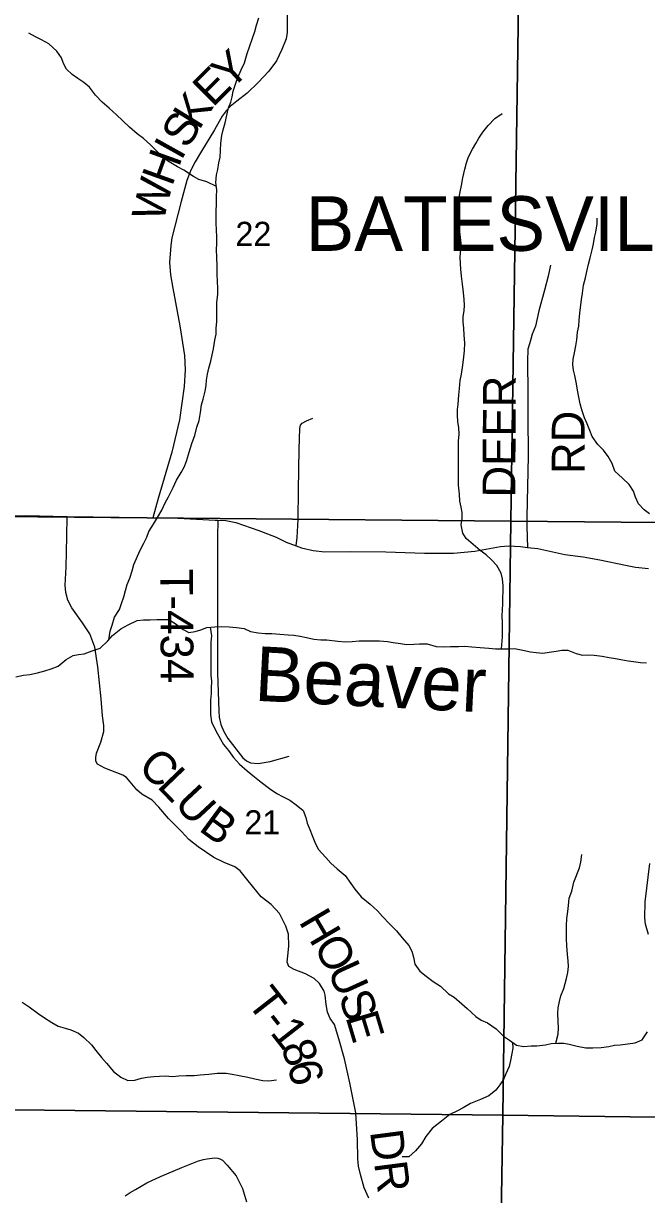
# Model space of a CAD drawing. Extents: x 2043100 to 2470832, y 443715 to 810583.
# Drawn here: x 2302542 to 2308244, y 693056 to 703774 of the extents above; entities that cross this region are included whole.
import ezdxf

# ---------------------------------------------------------------- set-up
doc = ezdxf.new("R2010")
doc.units = 0
for name, color, linetype in [('GM_X_Corporation_Text', 7, 'Continuous'), ('GM_X_County_Road', 7, 'Continuous'), ('GM_X_County_Road_Text', 7, 'Continuous'), ('GM_X_Minor_River', 7, 'Continuous'), ('GM_X_Minor_River_Text', 7, 'Continuous'), ('GM_X_Section', 7, 'Continuous'), ('GM_X_Section_Text', 7, 'Continuous'), ('GM_X_State_Route', 7, 'Continuous'), ('GM_X_Township_Road', 7, 'Continuous'), ('GM_X_Township_Road_Text', 7, 'Continuous')]:
    doc.layers.add(name, color=color, linetype=linetype)

msp = doc.modelspace()

# ---------------------------------------------------------------- linework, layer by layer
at = {"layer": 'GM_X_County_Road'}
msp.add_lwpolyline([(2304954, 703932), (2304956, 703759), (2304954, 703691), (2304945, 703633), (2304908, 703535), (2304857, 703431), (2304788, 703338), (2304691, 703234), (2304590, 703137), (2304495, 703062), (2304433, 703014), (2304396, 702974), (2304362, 702925), (2304291, 702799), (2304171, 702606), (2304114, 702508), (2304073, 702430), (2304038, 702338), (2303986, 702144), (2303899, 701812), (2303892, 701742), (2303879, 701586), (2303888, 701473), (2303909, 701351), (2303973, 701007), (2304017, 700734), (2304022, 700604), (2304014, 700452), (2303969, 700145), (2303900, 699851), (2303774, 699427), (2303726, 699250)], dxfattribs=at)
at = {"layer": 'GM_X_Minor_River'}
for points in [[(2303324, 698134), (2303336, 698211), (2303354, 698266), (2303376, 698340), (2303420, 698410), (2303439, 698464), (2303461, 698527), (2303477, 698583), (2303491, 698639), (2303515, 698697), (2303537, 698763), (2303553, 698822), (2303577, 698876), (2303607, 698948), (2303645, 699018), (2303671, 699073), (2303690, 699123), (2303732, 699193), (2303768, 699251), (2303808, 699320), (2303838, 699386), (2303870, 699442), (2303912, 699526), (2303942, 699593), (2303986, 699663), (2304012, 699713), (2304034, 699767), (2304053, 699828), (2304069, 699880), (2304087, 699938), (2304111, 700002), (2304129, 700080), (2304149, 700141), (2304161, 700213), (2304171, 700283), (2304187, 700335), (2304204, 700409), (2304214, 700460), (2304218, 700510), (2304226, 700564), (2304238, 700618), (2304256, 700682), (2304270, 700742), (2304282, 700797), (2304295, 700875), (2304305, 700931), (2304307, 700983), (2304311, 701047), (2304311, 701102), (2304313, 701162), (2304311, 701224), (2304321, 701292), (2304320, 701348), (2304318, 701416), (2304316, 701476), (2304316, 701555), (2304312, 701633), (2304310, 701705), (2304311, 701757), (2304311, 701819), (2304309, 701885), (2304307, 701946), (2304307, 702056), (2304309, 702120), (2304310, 702190), (2304312, 702252), (2304304, 702319), (2304310, 702389), (2304320, 702439), (2304330, 702499), (2304342, 702549), (2304345, 702611), (2304349, 702678), (2304359, 702750), (2304369, 702800), (2304389, 702866), (2304403, 702934), (2304419, 703001), (2304439, 703053), (2304452, 703103), (2304462, 703153), (2304486, 703229), (2304504, 703280), (2304536, 703350), (2304564, 703414), (2304590, 703499), (2304610, 703559), (2304639, 703639), (2304659, 703701), (2304675, 703757), (2304695, 703826)], [(2304309, 702283), (2304220, 702324), (2304148, 702346), (2304098, 702374), (2304011, 702432), (2303953, 702462), (2303861, 702516), (2303782, 702587), (2303706, 702663), (2303640, 702721), (2303582, 702763), (2303513, 702825), (2303451, 702883), (2303393, 702939), (2303327, 702999), (2303264, 703055), (2303202, 703117), (2303146, 703191), (2303094, 703233), (2303040, 703271), (2302989, 703307), (2302937, 703355), (2302909, 703409), (2302891, 703459), (2302847, 703521), (2302776, 703587), (2302706, 703623), (2302654, 703653), (2302592, 703686)], [(2306916, 698049), (2306926, 698161), (2306926, 698287), (2306924, 698352), (2306926, 698408), (2306930, 698462), (2306930, 698520), (2306932, 698576), (2306931, 698628), (2306925, 698692), (2306915, 698742), (2306873, 698812), (2306825, 698866), (2306775, 698912), (2306722, 698952), (2306594, 699060), (2306564, 699110), (2306549, 699186), (2306557, 699244), (2306557, 699297), (2306549, 699347), (2306535, 699401), (2306531, 699465), (2306523, 699549), (2306522, 699693), (2306524, 699761), (2306522, 699832), (2306522, 699892), (2306524, 699950), (2306528, 700014), (2306527, 700074), (2306517, 700132), (2306513, 700188), (2306515, 700241), (2306519, 700291), (2306525, 700371), (2306533, 700433), (2306540, 700505), (2306550, 700563), (2306564, 700646), (2306572, 700722), (2306578, 700778), (2306582, 700850), (2306575, 700922), (2306571, 700985), (2306565, 701041), (2306565, 701091), (2306575, 701145), (2306579, 701195), (2306575, 701247), (2306569, 701311), (2306560, 701389), (2306552, 701460), (2306546, 701526), (2306542, 701578), (2306538, 701636), (2306544, 701704), (2306547, 701760), (2306543, 701816), (2306537, 701867), (2306531, 701931), (2306523, 701999), (2306517, 702057), (2306519, 702113), (2306526, 702167), (2306540, 702232), (2306550, 702290), (2306564, 702360), (2306580, 702442), (2306596, 702500), (2306614, 702553), (2306652, 702623), (2306682, 702675), (2306709, 702725), (2306745, 702780), (2306795, 702840), (2306855, 702904), (2306923, 702951)], [(2308272, 699286), (2308222, 699322), (2308170, 699378), (2308142, 699438), (2308124, 699494), (2308085, 699556), (2308025, 699612), (2307955, 699676), (2307929, 699748), (2307894, 699810), (2307850, 699870), (2307798, 699920), (2307746, 699994), (2307724, 700050), (2307701, 700110), (2307677, 700164), (2307651, 700238), (2307637, 700294), (2307623, 700354), (2307613, 700418), (2307602, 700477), (2307588, 700551), (2307576, 700601), (2307570, 700653), (2307572, 700703), (2307584, 700759), (2307598, 700825), (2307605, 700880), (2307613, 700948), (2307623, 701004), (2307627, 701058), (2307635, 701122), (2307649, 701249), (2307657, 701307), (2307668, 701379), (2307684, 701445), (2307698, 701503), (2307714, 701570), (2307728, 701628), (2307746, 701702), (2307758, 701758), (2307768, 701814), (2307781, 701865), (2307791, 701941), (2307793, 701991)], [(2302473, 697794), (2302543, 697808), (2302601, 697816), (2302670, 697830), (2302738, 697849), (2302796, 697867), (2302860, 697891), (2302934, 697952), (2302996, 697990), (2303046, 698000), (2303098, 698006), (2303170, 698031), (2303244, 698057), (2303314, 698123), (2303358, 698173), (2303432, 698234), (2303502, 698270), (2303584, 698311), (2303642, 698317), (2303702, 698317), (2303764, 698319), (2303816, 698319), (2303873, 698318), (2303941, 698276), (2304003, 698226), (2304057, 698200), (2304115, 698208), (2304165, 698224), (2304221, 698247), (2304294, 698253), (2304354, 698255), (2304424, 698251), (2304492, 698247), (2304562, 698236), (2304620, 698210), (2304690, 698196), (2304754, 698190), (2304815, 698190), (2304889, 698185), (2304965, 698179), (2305015, 698175), (2305075, 698167), (2305131, 698155)], [(2304251, 698249), (2304262, 698168), (2304258, 698112), (2304256, 698052), (2304258, 698000), (2304256, 697930), (2304256, 697880), (2304258, 697810), (2304263, 697754), (2304261, 697691), (2304259, 697641), (2304255, 697581), (2304255, 697451), (2304263, 697383), (2304304, 697299), (2304344, 697225), (2304374, 697175), (2304418, 697119), (2304465, 697057), (2304519, 696995), (2304589, 696935), (2304657, 696879), (2304717, 696829), (2304794, 696773), (2304860, 696727), (2304920, 696697), (2304980, 696666), (2305039, 696624), (2305103, 696572), (2305125, 696506), (2305139, 696454), (2305163, 696396), (2305183, 696343), (2305210, 696281), (2305240, 696217), (2305310, 696141), (2305354, 696089), (2305413, 696036), (2305485, 695976), (2305539, 695904), (2305575, 695850), (2305633, 695782), (2305714, 695714), (2305782, 695654), (2305828, 695602), (2305893, 695534), (2305955, 695470), (2306007, 695404), (2306069, 695334), (2306097, 695282), (2306112, 695228), (2306124, 695166), (2306170, 695100), (2306226, 695056), (2306292, 695006), (2306359, 694964), (2306433, 694894), (2306485, 694861), (2306553, 694801), (2306604, 694759), (2306682, 694685), (2306732, 694653), (2306790, 694629), (2306868, 694573), (2306935, 694507), (2306989, 694469), (2307053, 694423), (2307117, 694410), (2307189, 694418), (2307239, 694418), (2307320, 694426), (2307370, 694438), (2307432, 694441), (2307486, 694441), (2307536, 694433), (2307610, 694413), (2307690, 694399), (2307754, 694398), (2307830, 694402), (2307899, 694410), (2307951, 694422), (2308003, 694427), (2308073, 694435), (2308141, 694445), (2308205, 694473), (2308253, 694544)], [(2305131, 698155), (2305199, 698139), (2305264, 698134), (2305318, 698132), (2305418, 698120), (2305488, 698116), (2305550, 698117), (2305614, 698123), (2305680, 698125), (2305799, 698125), (2305875, 698118), (2305927, 698110), (2305993, 698098), (2306049, 698090), (2306115, 698092), (2306167, 698097), (2306237, 698095), (2306320, 698071), (2306396, 698069), (2306450, 698071), (2306524, 698072), (2306582, 698074), (2306646, 698070), (2306722, 698064), (2306802, 698056), (2306861, 698051), (2306911, 698049), (2306981, 698051), (2307037, 698053), (2307113, 698039), (2307181, 698024), (2307233, 698016), (2307295, 698012), (2307354, 698020), (2307418, 698030), (2307468, 698037), (2307524, 698037), (2307600, 698009), (2307658, 697993), (2307714, 697997), (2307766, 697993), (2307837, 697984), (2307903, 697972), (2307959, 697962), (2308009, 697954), (2308075, 697942), (2308125, 697934), (2308189, 697925), (2308245, 697921)], [(2307413, 694440), (2307436, 694525), (2307437, 694583), (2307435, 694641), (2307431, 694715), (2307435, 694765), (2307447, 694822), (2307461, 694874), (2307487, 694942), (2307511, 695032), (2307524, 695088), (2307530, 695143), (2307526, 695195), (2307522, 695253), (2307516, 695333), (2307512, 695399), (2307511, 695515), (2307515, 695583), (2307525, 695648), (2307531, 695700), (2307537, 695768), (2307559, 695832), (2307579, 695916), (2307630, 696047), (2307644, 696097), (2307652, 696167)], [(2302532, 694817), (2302596, 694775), (2302677, 694714), (2302727, 694678), (2302801, 694630), (2302859, 694596), (2302923, 694578), (2302975, 694564), (2303046, 694532), (2303096, 694494), (2303164, 694427), (2303204, 694375), (2303258, 694311), (2303301, 694257), (2303365, 694183), (2303433, 694129), (2303497, 694099), (2303563, 694103), (2303624, 694121), (2303674, 694130), (2303736, 694136), (2303788, 694140), (2303840, 694142), (2303906, 694136), (2303964, 694141), (2304030, 694145), (2304106, 694147), (2304158, 694153), (2304239, 694158), (2304315, 694168), (2304397, 694166), (2304453, 694158), (2304515, 694147), (2304597, 694129), (2304659, 694115), (2304734, 694099), (2304788, 694097), (2304858, 694106)], [(2307018, 694449), (2307019, 694397), (2307011, 694347), (2306999, 694283), (2306987, 694229), (2306957, 694161), (2306936, 694110), (2306902, 694060), (2306866, 694010), (2306802, 693960), (2306726, 693927), (2306633, 693889), (2306565, 693849), (2306513, 693822), (2306443, 693790), (2306367, 693728), (2306283, 693659), (2306223, 693587), (2306186, 693519), (2306130, 693456), (2306070, 693400), (2306009, 693400)]]:
    msp.add_lwpolyline(points, dxfattribs=at)
at = {"layer": 'GM_X_Section'}
for points in [[(2301716, 704609), (2307083, 704576), (2307003, 699218), (2301672, 699268)], [(2307083, 704576), (2312456, 704490), (2312386, 699171), (2307003, 699218)], [(2307003, 699218), (2306930, 693781), (2301611, 693839), (2301672, 699268)], [(2312386, 699171), (2312292, 693713), (2306930, 693781), (2307003, 699218)], [(2301611, 693839), (2306930, 693781), (2306841, 688395), (2301544, 688414)], [(2306930, 693781), (2312292, 693713), (2312206, 688340), (2306841, 688395)]]:
    msp.add_lwpolyline(points, close=True, dxfattribs=at)
at = {"layer": 'GM_X_State_Route'}
for points in [[(2302435, 699267), (2302561, 699272), (2302943, 699263), (2303418, 699256), (2303726, 699250), (2303956, 699246), (2304297, 699229), (2304321, 699228), (2304393, 699225), (2304485, 699207), (2304696, 699134), (2304854, 699074), (2304946, 699028), (2305038, 698994), (2305088, 698975), (2305193, 698949), (2305299, 698939), (2305539, 698942), (2305859, 698939), (2306212, 698926), (2306478, 698926), (2306672, 698945), (2306908, 698988), (2306980, 698992), (2307092, 698986), (2307154, 698979), (2307248, 698969), (2307497, 698913), (2307663, 698892), (2307817, 698864), (2308050, 698817), (2308144, 698797), (2308262, 698787)], [(2308261, 695436), (2308235, 695530), (2308227, 695588), (2308230, 695734), (2308273, 696085)]]:
    msp.add_lwpolyline(points, dxfattribs=at)
at = {"layer": 'GM_X_Township_Road'}
for points in [[(2307365, 701561), (2307344, 701461), (2307310, 701333), (2307259, 701145), (2307227, 701003), (2307198, 700929), (2307184, 700885), (2307172, 700841), (2307157, 700793), (2307154, 700683), (2307159, 700394), (2307159, 700182), (2307160, 699813), (2307149, 699258), (2307150, 699169), (2307154, 698979)], [(2305038, 698994), (2305048, 699069), (2305056, 699233), (2305058, 699502), (2305066, 699878), (2305070, 700067), (2305078, 700099), (2305094, 700117), (2305133, 700138), (2305191, 700162)], [(2305703, 693022), (2305659, 693116), (2305627, 693240), (2305608, 693316), (2305602, 693382), (2305598, 693558), (2305583, 693805), (2305528, 694077), (2305480, 694298), (2305429, 694480), (2305389, 694612), (2305350, 694668), (2305326, 694726), (2305312, 694796), (2305304, 694880), (2305294, 694918), (2305252, 694988), (2305203, 695032), (2305123, 695076), (2305021, 695116), (2304971, 695144), (2304957, 695184), (2304963, 695240), (2304970, 695328), (2304968, 695440), (2304942, 695511), (2304885, 695627), (2304809, 695711), (2304719, 695782), (2304598, 695928), (2304524, 696018), (2304478, 696056), (2304378, 696096), (2304285, 696142), (2304141, 696238), (2304055, 696304), (2303988, 696380), (2303870, 696499), (2303782, 696601), (2303719, 696665), (2303625, 696721), (2303579, 696759), (2303519, 696833), (2303485, 696873), (2303453, 696893), (2303286, 696959), (2303220, 696995), (2303206, 697021), (2303206, 697055), (2303210, 697095), (2303249, 697197), (2303277, 697293), (2303277, 697348), (2303267, 697438), (2303254, 697594), (2303222, 697885), (2303195, 698065), (2303151, 698189), (2303082, 698287), (2302986, 698427), (2302948, 698497), (2302929, 698567), (2302925, 698633), (2302933, 698798), (2302940, 699080), (2302943, 699263)], [(2304321, 699228), (2304318, 699077), (2304317, 698783), (2304317, 698354), (2304318, 697831), (2304330, 697480), (2304332, 697425), (2304349, 697359), (2304375, 697293), (2304412, 697230), (2304549, 697053), (2304582, 697024), (2304620, 697006), (2304690, 697001), (2304800, 697018), (2304975, 697069)], [(2303473, 693043), (2303519, 693075), (2303569, 693103), (2303671, 693164), (2303795, 693222), (2303991, 693305), (2304145, 693364), (2304189, 693376), (2304223, 693384), (2304291, 693392), (2304321, 693390), (2304339, 693384), (2304363, 693370), (2304407, 693326), (2304488, 693228), (2304546, 693110), (2304584, 692990)]]:
    msp.add_lwpolyline(points, dxfattribs=at)

# ---------------------------------------------------------------- texts
at = {"layer": 'GM_X_Corporation_Text'}
msp.add_text('BATESVILLE', height=500, rotation=0, dxfattribs=at).set_placement((2305124, 701693))
at = {"layer": 'GM_X_County_Road_Text'}
for s, rotation, p in [('Y', 42.0286, (2304431, 703156)), ('E', 44.9394, (2304275, 703001)), ('K', 58.4402, (2304149, 702790)), ('S', 58.8659, (2304044, 702617)), ('I', 60.8438, (2303986, 702512)), ('H', 70.2425, (2303902, 702276)), ('W', 76.0973, (2303821, 701946))]:
    msp.add_text(s, height=300, rotation=rotation, dxfattribs=at).set_placement(p)
at = {"layer": 'GM_X_Minor_River_Text'}
msp.add_text('Beaver', height=500, rotation=357.0891, dxfattribs=at).set_placement((2304650, 697576))
at = {"layer": 'GM_X_Section_Text'}
for s, p in [('22', (2304482, 701738)), ('21', (2304564, 696352))]:
    msp.add_text(s, height=220.8, rotation=0, dxfattribs=at).set_placement(p)
at = {"layer": 'GM_X_Township_Road_Text'}
for s, rotation, p in [('DEER', 89.737, (2307043, 699435)), ('RD', 90, (2307677, 699650)), ('T-434', 270.2805, (2303794, 698783)), ('C', 317.877, (2303577, 696950)), ('L', 313.8848, (2303756, 696789)), ('U', 313.0213, (2303911, 696628)), ('B', 323.6848, (2304136, 696394)), ('H', 300.4452, (2305056, 695555)), ('O', 299.9898, (2305189, 695328)), ('U', 294.5528, (2305318, 695106)), ('T', 307.9885, (2304578, 694811)), ('S', 288.0834, (2305424, 694874)), ('-', 307.9961, (2304716, 694634)), ('E', 286.7095, (2305487, 694683)), ('1', 308.0179, (2304792, 694537)), ('8', 289.791, (2304894, 694413)), ('6', 284.2925, (2304954, 694247)), ('DR', 277.431, (2305713, 693633))]:
    msp.add_text(s, height=300, rotation=rotation, dxfattribs=at).set_placement(p)

doc.saveas('drawing.dxf')
